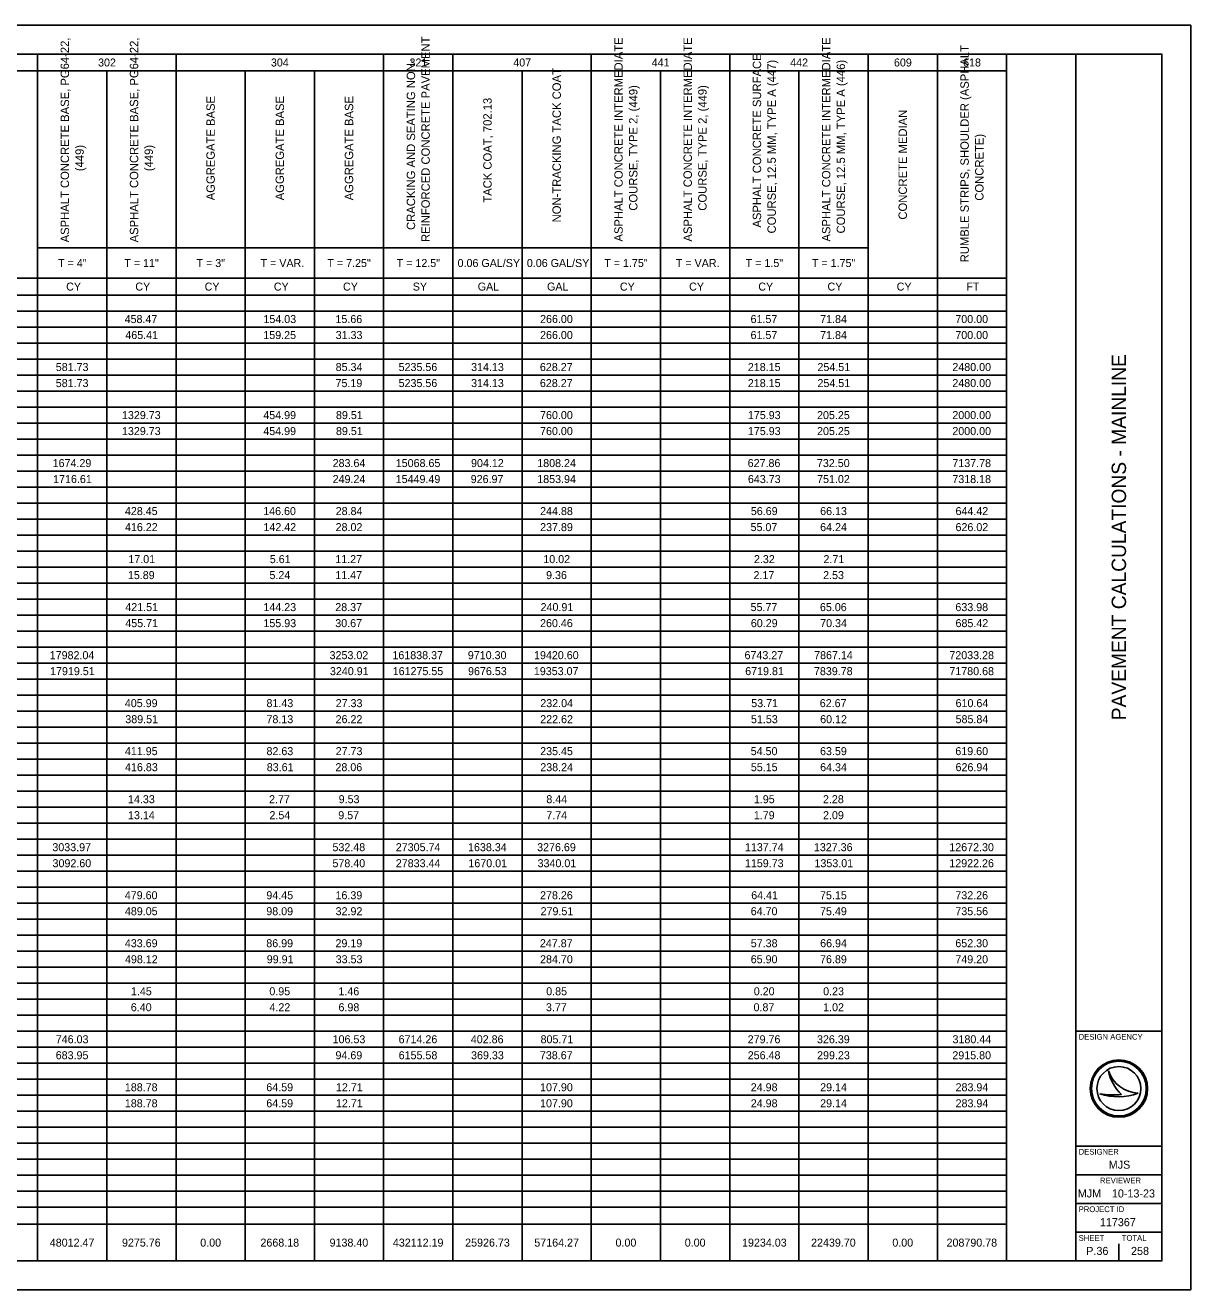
# Model space of a CAD drawing. Extents: x 0 to 34, y 0 to 22.
# Drawn here: x 13.72 to 34, y 0 to 22 of the extents above; entities that cross this region are included whole.
import ezdxf

# ---------------------------------------------------------------- set-up
doc = ezdxf.new("R2010")
doc.units = 0
for name, color, linetype in [('SH_Border', 7, 'Continuous'), ('SH_Cut_Line', 7, 'Continuous'), ('SH_Data', 7, 'Continuous'), ('SH_Text', 7, 'Continuous')]:
    doc.layers.add(name, color=color, linetype=linetype)

msp = doc.modelspace()

# ---------------------------------------------------------------- linework, layer by layer
at = {"layer": 'SH_Border'}
for p, q in [((32, 0.5), (32, 21.5)), ((32, 4.5), (33.5, 4.5)), ((32, 2.5), (33.5, 2.5)), ((32, 2), (33.5, 2)), ((32, 1.5), (33.5, 1.5)), ((32, 1), (33.5, 1))]:
    msp.add_line(p, q, dxfattribs=at)
msp.add_lwpolyline([(1.5, 21.5), (33.5, 21.5), (33.5, 0.5), (1.5, 0.5)], close=True, dxfattribs=at)
at = {"layer": 'SH_Cut_Line'}
msp.add_lwpolyline([(0, 0), (34, 0), (34, 22), (0, 22)], close=True, dxfattribs=at)
at = {"layer": 'SH_Data'}
for p, q in [((32.567, 3.81), (32.567, 3.81)), ((32.417, 3.41), (32.417, 3.41)), ((32.75, 3.5), (32.75, 3.5)), ((33.087, 3.419), (33.087, 3.419)), ((32.375, 0.675), (32.375, 0.675)), ((32.75, 0.5), (32.75, 0.8))]:
    msp.add_line(p, q, dxfattribs=at)
for radius in [0.5, 0.477, 0.477, 0.382]:
    msp.add_circle((32.75, 3.5), radius, dxfattribs=at)
for centre, radius, start, end in [((33.116, 3.998), 0.58, 198.9257, 198.9319), ((33.347, 3.97), 0.796, 191.6379, 191.6421), ((33.116, 3.998), 0.58, 198.9319, 267.1657), ((33.347, 3.97), 0.796, 191.6421, 226.0947), ((32.739, 4.37), 1.013, 251.4576, 290.0832), ((32.648, 4.654), 1.266, 259.4964, 259.4995), ((32.739, 4.37), 1.013, 251.4527, 251.4576), ((32.648, 4.654), 1.266, 259.4995, 276.6672)]:
    msp.add_arc(centre, radius, start, end, dxfattribs=at)
at = {"layer": 'SH_Text'}
for p, q in [((1.5, 21.5), (30.796, 21.5)), ((13.937, 21.5), (13.937, 0.5)), ((16.346, 21.5), (16.346, 0.5)), ((19.958, 21.5), (19.958, 0.5)), ((21.162, 21.5), (21.162, 0.5)), ((23.571, 21.5), (23.571, 0.5)), ((25.979, 21.5), (25.979, 0.5)), ((28.387, 21.5), (28.387, 0.5)), ((29.592, 21.5), (29.592, 0.5)), ((30.796, 21.5), (30.796, 0.5)), ((1.5, 21.205), (30.796, 21.205)), ((15.142, 21.205), (15.142, 0.5)), ((17.55, 21.205), (17.55, 0.5)), ((18.754, 21.205), (18.754, 0.5)), ((22.367, 21.205), (22.367, 0.5)), ((24.775, 21.205), (24.775, 0.5)), ((27.183, 21.205), (27.183, 0.5)), ((13.937, 18.126), (28.387, 18.126)), ((7.142, 17.601), (30.796, 17.601)), ((1.5, 17.307), (30.796, 17.307)), ((1.5, 17.028), (30.796, 17.028)), ((2.567, 16.75), (30.796, 16.75)), ((2.567, 16.471), (30.796, 16.471)), ((2.567, 16.193), (30.796, 16.193)), ((2.567, 15.914), (30.796, 15.914)), ((2.567, 15.636), (30.796, 15.636)), ((2.567, 15.357), (30.796, 15.357)), ((2.567, 15.079), (30.796, 15.079)), ((2.567, 14.8), (30.796, 14.8)), ((2.567, 14.522), (30.796, 14.522)), ((2.567, 14.243), (30.796, 14.243)), ((2.567, 13.965), (30.796, 13.965)), ((2.567, 13.686), (30.796, 13.686)), ((2.567, 13.408), (30.796, 13.408)), ((2.567, 13.129), (30.796, 13.129)), ((2.567, 12.851), (30.796, 12.851)), ((2.567, 12.573), (30.796, 12.573)), ((2.567, 12.294), (30.796, 12.294)), ((2.567, 12.016), (30.796, 12.016)), ((2.567, 11.737), (30.796, 11.737)), ((2.567, 11.459), (30.796, 11.459)), ((2.567, 11.18), (30.796, 11.18)), ((2.567, 10.902), (30.796, 10.902)), ((2.567, 10.623), (30.796, 10.623)), ((2.567, 10.345), (30.796, 10.345)), ((2.567, 10.066), (30.796, 10.066)), ((2.567, 9.788), (30.796, 9.788)), ((2.567, 9.509), (30.796, 9.509)), ((2.567, 9.231), (30.796, 9.231)), ((2.567, 8.952), (30.796, 8.952)), ((2.567, 8.674), (30.796, 8.674)), ((2.567, 8.395), (30.796, 8.395)), ((2.567, 8.117), (30.796, 8.117)), ((2.567, 7.839), (30.796, 7.839)), ((2.567, 7.56), (30.796, 7.56)), ((2.567, 7.282), (30.796, 7.282)), ((2.567, 7.003), (30.796, 7.003)), ((2.567, 6.725), (30.796, 6.725)), ((2.567, 6.446), (30.796, 6.446)), ((2.567, 6.168), (30.796, 6.168)), ((2.567, 5.889), (30.796, 5.889)), ((2.567, 5.611), (30.796, 5.611)), ((2.567, 5.332), (30.796, 5.332)), ((2.567, 5.054), (30.796, 5.054)), ((2.567, 4.775), (30.796, 4.775)), ((2.567, 4.497), (30.796, 4.497)), ((2.567, 4.218), (30.796, 4.218)), ((2.567, 3.94), (30.796, 3.94)), ((2.567, 3.661), (30.796, 3.661)), ((2.567, 3.383), (30.796, 3.383)), ((2.567, 3.105), (30.796, 3.105)), ((2.567, 2.826), (30.796, 2.826)), ((2.567, 2.548), (30.796, 2.548)), ((2.567, 2.269), (30.796, 2.269)), ((2.567, 1.991), (30.796, 1.991)), ((2.567, 1.712), (30.796, 1.712)), ((2.567, 1.434), (30.796, 1.434)), ((1.5, 1.139), (30.796, 1.139)), ((1.5, 0.5), (30.796, 0.5))]:
    msp.add_line(p, q, dxfattribs=at)

# ---------------------------------------------------------------- texts
at = {"layer": 'SH_Data'}
msp.add_text('PAVEMENT CALCULATIONS - MAINLINE', height=0.25, rotation=90, dxfattribs=at).set_placement((32.875, 9.908))
for s, height, p in [('DESIGN AGENCY', 0.1, (32.05, 4.35)), ('DESIGNER', 0.1, (32.05, 2.35)), ('MJS', 0.14, (32.574, 2.105)), ('REVIEWER', 0.1, (32.422, 1.85)), ('MJM', 0.14, (32.035, 1.605)), ('10-13-23', 0.14, (32.629, 1.605)), ('PROJECT ID', 0.1, (32.05, 1.35)), ('117367', 0.14, (32.42, 1.105)), ('SHEET', 0.1, (32.05, 0.85)), ('TOTAL', 0.1, (32.8, 0.85)), ('P.36', 0.14, (32.183, 0.605)), ('258', 0.14, (32.962, 0.605))]:
    msp.add_text(s, height=height, dxfattribs=at).set_placement(p)
at = {"layer": 'SH_Text'}
for s, height, p in [('REINFORCED CONCRETE PAVEMENT', 0.14622, (20.761, 18.23)), ('ASPHALT CONCRETE INTERMEDIATE ', 0.14622, (24.118, 18.237)), ('ASPHALT CONCRETE INTERMEDIATE ', 0.14622, (25.322, 18.237)), ('ASPHALT CONCRETE INTERMEDIATE ', 0.14622, (27.731, 18.237)), ('ASPHALT CONCRETE BASE, PG64-22, ', 0.14622, (14.485, 18.223)), ('ASPHALT CONCRETE BASE, PG64-22, ', 0.14622, (15.689, 18.223)), ('RUMBLE STRIPS, SHOULDER (ASPHALT ', 0.14622, (30.139, 17.876)), ('CRACKING AND SEATING NON-', 0.14622, (20.506, 18.439)), ('ASPHALT CONCRETE SURFACE ', 0.14622, (26.526, 18.48)), ('COURSE, 12.5 MM, TYPE A (447)', 0.14622, (26.782, 18.378)), ('COURSE, 12.5 MM, TYPE A (446)', 0.14622, (27.986, 18.378)), ('NON-TRACKING TACK COAT', 0.14622, (23.042, 18.571)), ('COURSE, TYPE 2, (449)', 0.14622, (24.374, 18.774)), ('COURSE, TYPE 2, (449)', 0.14622, (25.578, 18.774)), ('AGGREGATE BASE', 0.14622, (17.021, 18.955)), ('AGGREGATE BASE', 0.14622, (18.225, 18.955)), ('AGGREGATE BASE', 0.14622, (19.429, 18.955)), ('TACK COAT, 702.13', 0.14622, (21.838, 18.913)), ('CONCRETE MEDIAN', 0.14622, (29.063, 18.619)), ('CONCRETE)', 0.1462, (30.395, 18.948)), ('(449)', 0.1462, (14.741, 19.462)), ('(449)', 0.1462, (15.945, 19.462))]:
    msp.add_text(s, height=height, rotation=90, dxfattribs=at).set_placement(p)
for s, height, p in [('302', 0.1392, (14.99, 21.283)), ('304', 0.1392, (17.997, 21.283)), ('321', 0.1392, (20.408, 21.283)), ('407', 0.1392, (22.214, 21.283)), ('441', 0.1392, (24.623, 21.283)), ('442', 0.1392, (27.032, 21.283)), ('609', 0.1392, (28.837, 21.283)), ('618', 0.1392, (30.04, 21.283)), ('T = 4"', 0.1392, (14.295, 17.794)), ('T = 11"', 0.1392, (15.447, 17.794)), ('T = 3"', 0.1392, (16.703, 17.794)), ('T = VAR.', 0.1392, (17.817, 17.794)), ('T = 7.25"', 0.1392, (18.98, 17.794)), ('T = 12.5"', 0.1392, (20.185, 17.794)), ('0.06 GAL/SY', 0.13924, (21.245, 17.794)), ('0.06 GAL/SY', 0.13924, (22.45, 17.794)), ('T = 1.75"', 0.1392, (23.797, 17.794)), ('T = VAR.', 0.1392, (25.042, 17.794)), ('T = 1.5"', 0.1392, (26.258, 17.794)), ('T = 1.75"', 0.1392, (27.41, 17.794)), ('CY', 0.1392, (14.435, 17.384)), ('CY', 0.1392, (15.639, 17.384)), ('CY', 0.1392, (16.844, 17.384)), ('CY', 0.1392, (18.048, 17.384)), ('CY', 0.1392, (19.252, 17.384)), ('SY', 0.1392, (20.465, 17.384)), ('GAL', 0.1392, (21.596, 17.384)), ('GAL', 0.1392, (22.801, 17.384)), ('CY', 0.1392, (24.069, 17.384)), ('CY', 0.1392, (25.273, 17.384)), ('CY', 0.1392, (26.477, 17.384)), ('CY', 0.1392, (27.681, 17.384)), ('CY', 0.1392, (28.885, 17.384)), ('FT', 0.1392, (30.096, 17.384)), ('458.47', 0.1392, (15.452, 16.819)), ('154.03', 0.1392, (17.867, 16.819)), ('15.66', 0.1392, (19.12, 16.819)), ('266.00', 0.1392, (22.68, 16.819)), ('61.57', 0.1392, (26.342, 16.819)), ('71.84', 0.1392, (27.553, 16.819)), ('700.00', 0.1392, (29.905, 16.819)), ('465.41', 0.1392, (15.464, 16.541)), ('159.25', 0.1392, (17.865, 16.541)), ('31.33', 0.1392, (19.124, 16.541)), ('266.00', 0.1392, (22.68, 16.541)), ('61.57', 0.1392, (26.342, 16.541)), ('71.84', 0.1392, (27.553, 16.541)), ('700.00', 0.1392, (29.905, 16.541)), ('581.73', 0.1392, (14.254, 15.984)), ('85.34', 0.1392, (19.124, 15.984)), ('5235.56', 0.1392, (20.219, 15.984)), ('314.13', 0.1392, (21.48, 15.984)), ('628.27', 0.1392, (22.677, 15.984)), ('218.15', 0.1392, (26.295, 15.984)), ('254.51', 0.1392, (27.506, 15.984)), ('2480.00', 0.1392, (29.853, 15.984)), ('581.73', 0.1392, (14.254, 15.705)), ('75.19', 0.1392, (19.121, 15.705)), ('5235.56', 0.1392, (20.219, 15.705)), ('314.13', 0.1392, (21.48, 15.705)), ('628.27', 0.1392, (22.677, 15.705)), ('218.15', 0.1392, (26.295, 15.705)), ('254.51', 0.1392, (27.506, 15.705)), ('2480.00', 0.1392, (29.853, 15.705)), ('1329.73', 0.1392, (15.406, 15.148)), ('454.99', 0.1392, (17.865, 15.148)), ('89.51', 0.1392, (19.129, 15.148)), ('760.00', 0.1392, (22.68, 15.148)), ('175.93', 0.1392, (26.296, 15.148)), ('205.25', 0.1392, (27.499, 15.148)), ('2000.00', 0.1392, (29.853, 15.148)), ('1329.73', 0.1392, (15.406, 14.87)), ('454.99', 0.1392, (17.865, 14.87)), ('89.51', 0.1392, (19.129, 14.87)), ('760.00', 0.1392, (22.68, 14.87)), ('175.93', 0.1392, (26.296, 14.87)), ('205.25', 0.1392, (27.499, 14.87)), ('2000.00', 0.1392, (29.853, 14.87)), ('1674.29', 0.1392, (14.2, 14.313)), ('283.64', 0.1392, (19.071, 14.313)), ('15068.65', 0.1392, (20.169, 14.313)), ('904.12', 0.1392, (21.479, 14.313)), ('1808.24', 0.1392, (22.631, 14.313)), ('627.86', 0.1392, (26.292, 14.313)), ('732.50', 0.1392, (27.497, 14.313)), ('7137.78', 0.1392, (29.853, 14.313)), ('1716.61', 0.1392, (14.208, 14.035)), ('249.24', 0.1392, (19.071, 14.035)), ('15449.49', 0.1392, (20.168, 14.035)), ('926.97', 0.1392, (21.473, 14.035)), ('1853.94', 0.1392, (22.631, 14.035)), ('643.73', 0.1392, (26.296, 14.035)), ('751.02', 0.1392, (27.5, 14.035)), ('7318.18', 0.1392, (29.853, 14.035)), ('428.45', 0.1392, (15.457, 13.478)), ('146.60', 0.1392, (17.863, 13.478)), ('28.84', 0.1392, (19.124, 13.478)), ('244.88', 0.1392, (22.681, 13.478)), ('56.69', 0.1392, (26.347, 13.478)), ('66.13', 0.1392, (27.553, 13.478)), ('644.42', 0.1392, (29.908, 13.478)), ('416.22', 0.1392, (15.458, 13.199)), ('142.42', 0.1392, (17.867, 13.199)), ('28.02', 0.1392, (19.123, 13.199)), ('237.89', 0.1392, (22.681, 13.199)), ('55.07', 0.1392, (26.342, 13.199)), ('64.24', 0.1392, (27.553, 13.199)), ('626.02', 0.1392, (29.908, 13.199)), ('17.01', 0.1392, (15.517, 12.642)), ('5.61', 0.1392, (17.978, 12.642)), ('11.27', 0.1392, (19.117, 12.642)), ('10.02', 0.1392, (22.736, 12.642)), ('2.32', 0.1392, (26.401, 12.642)), ('2.71', 0.1392, (27.611, 12.642)), ('15.89', 0.1392, (15.509, 12.364)), ('5.24', 0.1392, (17.972, 12.364)), ('11.47', 0.1392, (19.117, 12.364)), ('9.36', 0.1392, (22.785, 12.364)), ('2.17', 0.1392, (26.394, 12.364)), ('2.53', 0.1392, (27.605, 12.364)), ('421.51', 0.1392, (15.464, 11.807)), ('144.23', 0.1392, (17.867, 11.807)), ('28.37', 0.1392, (19.117, 11.807)), ('240.91', 0.1392, (22.689, 11.807)), ('55.77', 0.1392, (26.342, 11.807)), ('65.06', 0.1392, (27.549, 11.807)), ('633.98', 0.1392, (29.906, 11.807)), ('455.71', 0.1392, (15.464, 11.528)), ('155.93', 0.1392, (17.867, 11.528)), ('30.67', 0.1392, (19.117, 11.528)), ('260.46', 0.1392, (22.68, 11.528)), ('60.29', 0.1392, (26.347, 11.528)), ('70.34', 0.1392, (27.553, 11.528)), ('685.42', 0.1392, (29.908, 11.528)), ('17982.04', 0.1392, (14.149, 10.971)), ('3253.02', 0.1392, (19.018, 10.971)), ('161838.37', 0.1392, (20.111, 10.971)), ('9710.30', 0.1392, (21.423, 10.971)), ('19420.60', 0.1392, (22.575, 10.971)), ('6743.27', 0.1392, (26.237, 10.971)), ('7867.14', 0.1392, (27.448, 10.971)), ('72033.28', 0.1392, (29.801, 10.971)), ('17919.51', 0.1392, (14.155, 10.693)), ('3240.91', 0.1392, (19.024, 10.693)), ('161275.55', 0.1392, (20.116, 10.693)), ('9676.53', 0.1392, (21.427, 10.693)), ('19353.07', 0.1392, (22.572, 10.693)), ('6719.81', 0.1392, (26.249, 10.693)), ('7839.78', 0.1392, (27.445, 10.693)), ('71780.68', 0.1392, (29.801, 10.693)), ('405.99', 0.1392, (15.456, 10.136)), ('81.43', 0.1392, (17.92, 10.136)), ('27.33', 0.1392, (19.124, 10.136)), ('232.04', 0.1392, (22.684, 10.136)), ('53.71', 0.1392, (26.354, 10.136)), ('62.67', 0.1392, (27.546, 10.136)), ('610.64', 0.1392, (29.909, 10.136)), ('389.51', 0.1392, (15.464, 9.857)), ('78.13', 0.1392, (17.92, 9.857)), ('26.22', 0.1392, (19.123, 9.857)), ('222.62', 0.1392, (22.683, 9.857)), ('51.53', 0.1392, (26.349, 9.857)), ('60.12', 0.1392, (27.553, 9.857)), ('585.84', 0.1392, (29.909, 9.857)), ('411.95', 0.1392, (15.457, 9.301)), ('82.63', 0.1392, (17.92, 9.301)), ('27.73', 0.1392, (19.124, 9.301)), ('235.45', 0.1392, (22.682, 9.301)), ('54.50', 0.1392, (26.345, 9.301)), ('63.59', 0.1392, (27.551, 9.301)), ('619.60', 0.1392, (29.905, 9.301)), ('416.83', 0.1392, (15.459, 9.022)), ('83.61', 0.1392, (17.925, 9.022)), ('28.06', 0.1392, (19.12, 9.022)), ('238.24', 0.1392, (22.684, 9.022)), ('55.15', 0.1392, (26.347, 9.022)), ('64.34', 0.1392, (27.553, 9.022)), ('626.94', 0.1392, (29.909, 9.022)), ('14.33', 0.1392, (15.511, 8.465)), ('2.77', 0.1392, (17.965, 8.465)), ('9.53', 0.1392, (19.176, 8.465)), ('8.44', 0.1392, (22.789, 8.465)), ('1.95', 0.1392, (26.4, 8.465)), ('2.28', 0.1392, (27.602, 8.465)), ('13.14', 0.1392, (15.511, 8.187)), ('2.54', 0.1392, (17.972, 8.187)), ('9.57', 0.1392, (19.169, 8.187)), ('7.74', 0.1392, (22.789, 8.187)), ('1.79', 0.1392, (26.399, 8.187)), ('2.09', 0.1392, (27.603, 8.187)), ('3033.97', 0.1392, (14.195, 7.63)), ('532.48', 0.1392, (19.068, 7.63)), ('27305.74', 0.1392, (20.17, 7.63)), ('1638.34', 0.1392, (21.427, 7.63)), ('3276.69', 0.1392, (22.629, 7.63)), ('1137.74', 0.1392, (26.244, 7.63)), ('1327.36', 0.1392, (27.444, 7.63)), ('12672.30', 0.1392, (29.8, 7.63)), ('3092.60', 0.1392, (14.198, 7.351)), ('578.40', 0.1392, (19.068, 7.351)), ('27833.44', 0.1392, (20.17, 7.351)), ('1670.01', 0.1392, (21.433, 7.351)), ('3340.01', 0.1392, (22.637, 7.351)), ('1159.73', 0.1392, (26.244, 7.351)), ('1353.01', 0.1392, (27.454, 7.351)), ('12922.26', 0.1392, (29.8, 7.351)), ('479.60', 0.1392, (15.455, 6.794)), ('94.45', 0.1392, (17.918, 6.794)), ('16.39', 0.1392, (19.121, 6.794)), ('278.26', 0.1392, (22.68, 6.794)), ('64.41', 0.1392, (26.354, 6.794)), ('75.15', 0.1392, (27.551, 6.794)), ('732.26', 0.1392, (29.905, 6.794)), ('489.05', 0.1392, (15.457, 6.516)), ('98.09', 0.1392, (17.917, 6.516)), ('32.92', 0.1392, (19.123, 6.516)), ('279.51', 0.1392, (22.689, 6.516)), ('64.70', 0.1392, (26.345, 6.516)), ('75.49', 0.1392, (27.551, 6.516)), ('735.56', 0.1392, (29.905, 6.516)), ('433.69', 0.1392, (15.456, 5.959)), ('86.99', 0.1392, (17.917, 5.959)), ('29.19', 0.1392, (19.121, 5.959)), ('247.87', 0.1392, (22.677, 5.959)), ('57.38', 0.1392, (26.346, 5.959)), ('66.94', 0.1392, (27.553, 5.959)), ('652.30', 0.1392, (29.905, 5.959)), ('498.12', 0.1392, (15.458, 5.68)), ('99.91', 0.1392, (17.925, 5.68)), ('33.53', 0.1392, (19.124, 5.68)), ('284.70', 0.1392, (22.68, 5.68)), ('65.90', 0.1392, (26.345, 5.68)), ('76.89', 0.1392, (27.551, 5.68)), ('749.20', 0.1392, (29.905, 5.68)), ('1.45', 0.1392, (15.562, 5.123)), ('0.95', 0.1392, (17.97, 5.123)), ('1.46', 0.1392, (19.172, 5.123)), ('0.85', 0.1392, (22.787, 5.123)), ('0.20', 0.1392, (26.398, 5.123)), ('0.23', 0.1392, (27.605, 5.123)), ('6.40', 0.1392, (15.56, 4.845)), ('4.22', 0.1392, (17.972, 4.845)), ('6.98', 0.1392, (19.173, 4.845)), ('3.77', 0.1392, (22.782, 4.845)), ('0.87', 0.1392, (26.394, 4.845)), ('1.02', 0.1392, (27.605, 4.845)), ('746.03', 0.1392, (14.254, 4.288)), ('106.53', 0.1392, (19.071, 4.288)), ('6714.26', 0.1392, (20.219, 4.288)), ('402.86', 0.1392, (21.475, 4.288)), ('805.71', 0.1392, (22.689, 4.288)), ('279.76', 0.1392, (26.292, 4.288)), ('326.39', 0.1392, (27.498, 4.288)), ('3180.44', 0.1392, (29.856, 4.288)), ('683.95', 0.1392, (14.253, 4.01)), ('94.69', 0.1392, (19.121, 4.01)), ('6155.58', 0.1392, (20.22, 4.01)), ('369.33', 0.1392, (21.48, 4.01)), ('738.67', 0.1392, (22.677, 4.01)), ('256.48', 0.1392, (26.293, 4.01)), ('299.23', 0.1392, (27.5, 4.01)), ('2915.80', 0.1392, (29.853, 4.01)), ('188.78', 0.1392, (15.456, 3.453)), ('64.59', 0.1392, (17.917, 3.453)), ('12.71', 0.1392, (19.129, 3.453)), ('107.90', 0.1392, (22.68, 3.453)), ('24.98', 0.1392, (26.346, 3.453)), ('29.14', 0.1392, (27.553, 3.453)), ('283.94', 0.1392, (29.909, 3.453)), ('188.78', 0.1392, (15.456, 3.174)), ('64.59', 0.1392, (17.917, 3.174)), ('12.71', 0.1392, (19.129, 3.174)), ('107.90', 0.1392, (22.68, 3.174)), ('24.98', 0.1392, (26.346, 3.174)), ('29.14', 0.1392, (27.553, 3.174)), ('283.94', 0.1392, (29.909, 3.174)), ('48012.47', 0.1392, (14.15, 0.75)), ('9275.76', 0.1392, (15.406, 0.75)), ('0.00', 0.1392, (16.768, 0.75)), ('2668.18', 0.1392, (17.815, 0.75)), ('9138.40', 0.1392, (19.018, 0.75)), ('432112.19', 0.1392, (20.119, 0.75)), ('25926.73', 0.1392, (21.377, 0.75)), ('57164.27', 0.1392, (22.58, 0.75)), ('0.00', 0.1392, (23.993, 0.75)), ('0.00', 0.1392, (25.197, 0.75)), ('19234.03', 0.1392, (26.194, 0.75)), ('22439.70', 0.1392, (27.395, 0.75)), ('0.00', 0.1392, (28.809, 0.75)), ('208790.78', 0.1392, (29.752, 0.75))]:
    msp.add_text(s, height=height, dxfattribs=at).set_placement(p)

doc.saveas('drawing.dxf')
